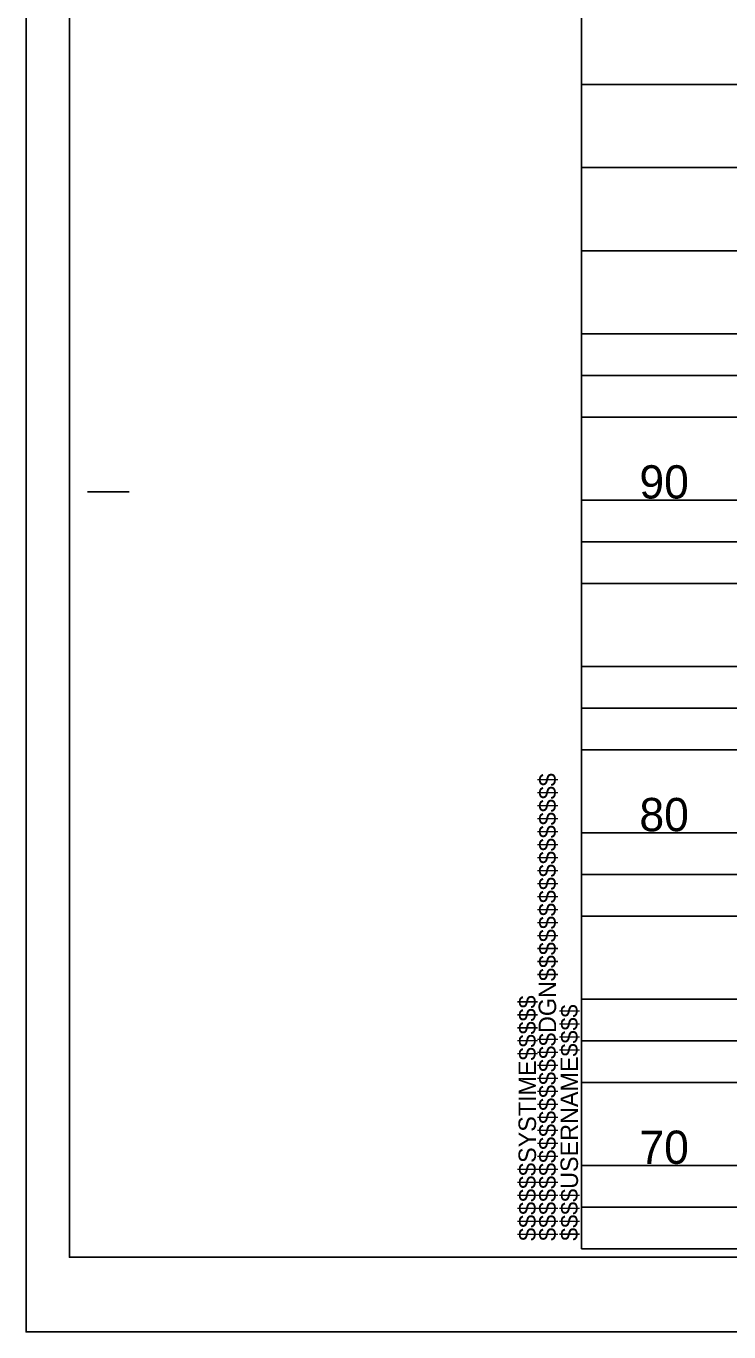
# Model space of a CAD drawing. Extents: x 2345490 to 2445302, y 465165 to 573888.
# Drawn here: x 2381549.8 to 2381761.1, y 510404.4 to 510796.9 of the extents above; entities that cross this region are included whole.
import ezdxf

# ---------------------------------------------------------------- set-up
doc = ezdxf.new("R2010")
doc.units = 0
for name, color, linetype in [('Old_Level_18', 7, 'Continuous'), ('Old_Level_40', 7, 'Continuous'), ('Old_Level_41', 7, 'Continuous'), ('Old_Level_42', 7, 'Continuous'), ('Old_Level_50', 7, 'Continuous'), ('Old_Level_51', 7, 'Continuous'), ('Old_Level_52', 7, 'Continuous'), ('Old_Level_57', 7, 'Continuous'), ('Old_Level_62', 7, 'Continuous')]:
    doc.layers.add(name, color=color, linetype=linetype)

msp = doc.modelspace()

# ---------------------------------------------------------------- linework, layer by layer
at = {"layer": 'Old_Level_18'}
msp.add_line((2381716.79875, 510429.3835), (2381716.79875, 510429.3835), dxfattribs=at)
msp.add_line((2381716.79875, 510429.3835), (2381716.79875, 510429.3835), dxfattribs=at)
msp.add_lwpolyline([(2383216.79875, 511479.3835), (2381716.79875, 511479.3835), (2381716.79875, 510429.3835), (2383216.79875, 510429.3835)], close=True, dxfattribs=at)
at = {"layer": 'Old_Level_40'}
msp.add_line((2381716.79875, 510429.3835), (2381716.79875, 510429.3835), dxfattribs=at)
msp.add_line((2381716.79875, 510429.3835), (2381716.79875, 510429.3835), dxfattribs=at)
msp.add_line((2381716.79875, 510429.3835), (2381716.79875, 510429.3835), dxfattribs=at)
msp.add_line((2381716.79875, 510429.3835), (2381716.79875, 510429.3835), dxfattribs=at)
at = {"layer": 'Old_Level_41'}
for p, q in [((2381568.29875, 510656.8835), (2381580.79875, 510656.8835)), ((2383216.79875, 510454.3835), (2381716.79875, 510454.3835))]:
    msp.add_line(p, q, dxfattribs=at)
for points in [[(2383216.79875, 510779.3835), (2381716.79875, 510779.3835), (2381716.79875, 510729.3835), (2383216.79875, 510729.3835)], [(2383216.79875, 510704.3835), (2381716.79875, 510704.3835), (2381716.79875, 510754.3835), (2383216.79875, 510754.3835)], [(2383216.79875, 510679.3835), (2381716.79875, 510679.3835), (2381716.79875, 510629.3835), (2383216.79875, 510629.3835)], [(2383216.79875, 510579.3835), (2381716.79875, 510579.3835), (2381716.79875, 510529.3835), (2383216.79875, 510529.3835)], [(2383216.79875, 510504.3835), (2381716.79875, 510504.3835), (2381716.79875, 510554.3835), (2383216.79875, 510554.3835)], [(2383216.79875, 510479.3835), (2381716.79875, 510479.3835)], [(2381754.29875, 510429.3835), (2381754.29875, 510429.3835)]]:
    msp.add_lwpolyline(points, dxfattribs=at)
at = {"layer": 'Old_Level_42'}
msp.add_lwpolyline([(2383216.79875, 510604.3835), (2381716.79875, 510604.3835), (2381716.79875, 510654.3835), (2383216.79875, 510654.3835)], dxfattribs=at)
at = {"layer": 'Old_Level_50'}
msp.add_line((2381549.79875, 510404.3835), (2381549.79875, 510404.3835), dxfattribs=at)
msp.add_lwpolyline([(2383229.29875, 511481.9335), (2381562.79875, 511481.9335), (2381562.79875, 510426.8335), (2383229.29875, 510426.8335)], close=True, dxfattribs=at)
at = {"layer": 'Old_Level_51'}
msp.add_lwpolyline([(2383233.79875, 511504.3835), (2381549.79875, 511504.3835), (2381549.79875, 510404.3835), (2383233.79875, 510404.3835)], close=True, dxfattribs=at)
at = {"layer": 'Old_Level_52'}
msp.add_line((2381562.79875, 510426.8335), (2381562.79875, 510426.8335), dxfattribs=at)
at = {"layer": 'Old_Level_57'}
for p, q in [((2381716.79925, 510691.88375), (2383066.79875, 510691.88375)), ((2381716.79925, 510641.88375), (2383066.79875, 510641.88375)), ((2381716.79925, 510591.88375), (2383066.79875, 510591.88375)), ((2381716.79925, 510541.88375), (2383066.79875, 510541.88375)), ((2381716.799, 510491.88375), (2383066.79875, 510491.88375)), ((2381716.79925, 510441.88375), (2383066.79875, 510441.88375))]:
    msp.add_line(p, q, dxfattribs=at)

# ---------------------------------------------------------------- texts
at = {"layer": 'Old_Level_41'}
for s, p in [('$$$$$$$$$$$$$$$$DGN$$$$$$$$$$$$$$$$', (2381709.14875, 510431.746)), ('$$$$$$SYSTIME$$$$$', (2381703.09875, 510431.746)), ('$$$$USERNAME$$$$', (2381715.72375, 510431.7585))]:
    msp.add_text(s, height=5.25, rotation=90, dxfattribs=at).set_placement(p)
at = {"layer": 'Old_Level_62'}
for s, p in [('90', (2381734.18536, 510654.8835)), ('80', (2381734.18536, 510554.8835)), ('70', (2381734.18536, 510454.8835))]:
    msp.add_text(s, height=10, dxfattribs=at).set_placement(p)

doc.saveas('drawing.dxf')
